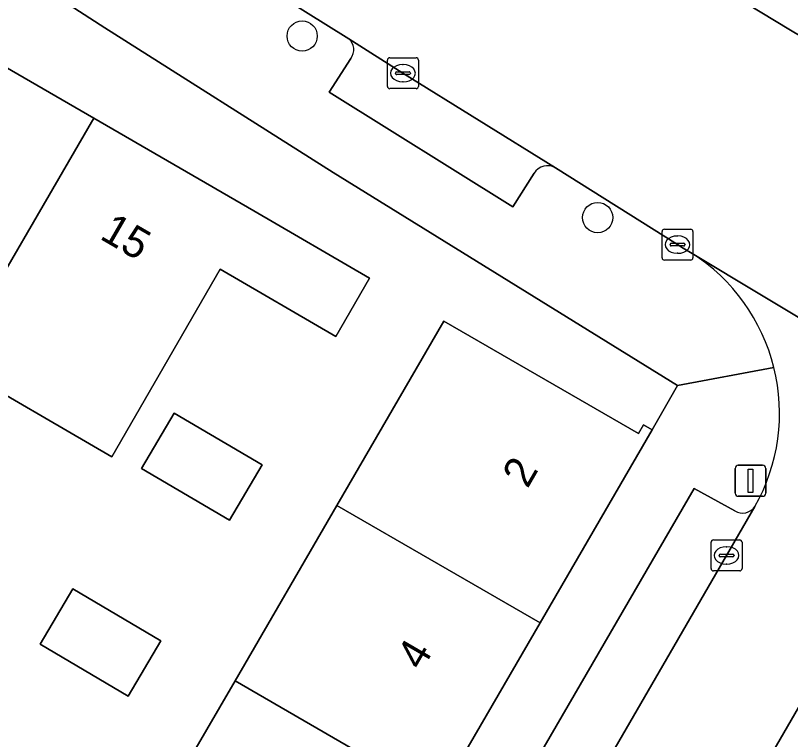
# Model space of a CAD drawing. Extents: x 160023 to 161302, y 384750 to 385707.
# Drawn here: x 160328.19 to 160353.25, y 385096.97 to 385120.37 of the extents above; entities that cross this region are included whole.
import ezdxf

# ---------------------------------------------------------------- set-up
doc = ezdxf.new("R2010")
doc.units = 0
for name, color, linetype in [('IMGEO_Boom', 7, 'Continuous'), ('IMGEO_Erf', 7, 'Continuous'), ('IMGEO_Kolk', 7, 'Continuous'), ('IMGEO_Lichtmast', 7, 'Continuous'), ('IMGEO_Pand', 7, 'Continuous'), ('IMGEO_Pand_nummerreeks', 7, 'Continuous'), ('IMGEO_Parkeervlak_open', 7, 'Continuous'), ('IMGEO_Rijbaan_lokaal_gesloten', 7, 'Continuous'), ('IMGEO_Rijbaan_lokaal_open', 7, 'Continuous'), ('IMGEO_Voetpad_open', 7, 'Continuous')]:
    doc.layers.add(name, color=color, linetype=linetype)

msp = doc.modelspace()

# ---------------------------------------------------------------- linework, layer by layer
at = {"layer": 'IMGEO_Boom'}
for centre in [(160337.46, 385119.709), (160347.014, 385113.841)]:
    msp.add_circle(centre, 0.489, dxfattribs=at)
at = {"layer": 'IMGEO_Erf'}
for points in [[(160324.913, 385073.741), (160330.09, 385070.735), (160334.083, 385077.616), (160332.317, 385078.627), (160331.779, 385077.69), (160328.34, 385079.651), (160329.434, 385081.559), (160332.868, 385079.588), (160335.098, 385083.409), (160328.525, 385087.223), (160331.975, 385093.164), (160335.29, 385098.871), (160338.579, 385104.535), (160342.039, 385110.493), (160348.337, 385106.863), (160348.498, 385107.138), (160348.774, 385106.977), (160349.593, 385108.411), (160338.466, 385115.299), (160331.075, 385119.978), (160323.23, 385125.041)], [(160320.863, 385122.761), (160325.8, 385119.903), (160330.722, 385117.054), (160335.895, 385114.06), (160339.64, 385111.886), (160338.546, 385110.001), (160334.808, 385112.175), (160331.31, 385106.11), (160326.105, 385109.12), (160321.174, 385111.972), (160316.25, 385114.819), (160314.601, 385111.992), (160309.619, 385114.882), (160311.258, 385117.706), (160306.266, 385120.593)]]:
    msp.add_lwpolyline(points, dxfattribs=at)
for points in [[(160332.264, 385105.735), (160333.316, 385107.522), (160336.163, 385105.848), (160335.111, 385104.06)], [(160328.987, 385100.05), (160330.039, 385101.838), (160332.886, 385100.163), (160331.835, 385098.375)]]:
    msp.add_lwpolyline(points, close=True, dxfattribs=at)
at = {"layer": 'IMGEO_Kolk'}
for p, q in [((160340.217, 385118.082), (160340.217, 385118.934)), ((160340.292, 385119.008), (160341.144, 385119.008)), ((160341.218, 385118.934), (160341.218, 385118.082)), ((160340.705, 385118.788), (160340.73, 385118.788)), ((160340.476, 385118.502), (160340.476, 385118.514)), ((160340.914, 385118.465), (160340.516, 385118.465)), ((160340.519, 385118.551), (160340.917, 385118.551)), ((160340.96, 385118.514), (160340.96, 385118.502)), ((160340.728, 385118.228), (160340.703, 385118.228)), ((160341.144, 385118.008), (160340.292, 385118.008)), ((160349.171, 385113.466), (160350.023, 385113.466)), ((160349.096, 385112.54), (160349.096, 385113.392)), ((160349.584, 385113.246), (160349.609, 385113.246)), ((160350.097, 385113.392), (160350.097, 385112.54)), ((160349.355, 385112.96), (160349.355, 385112.972)), ((160349.793, 385112.923), (160349.395, 385112.923)), ((160349.398, 385113.009), (160349.796, 385113.009)), ((160349.839, 385112.972), (160349.839, 385112.96)), ((160349.607, 385112.686), (160349.582, 385112.686)), ((160350.023, 385112.466), (160349.171, 385112.466)), ((160350.756, 385103.421), (160351.608, 385103.421)), ((160350.681, 385102.495), (160350.681, 385103.347)), ((160351.169, 385103.201), (160351.194, 385103.201)), ((160351.682, 385103.347), (160351.682, 385102.495)), ((160350.94, 385102.915), (160350.94, 385102.927)), ((160351.378, 385102.878), (160350.98, 385102.878)), ((160350.983, 385102.964), (160351.381, 385102.964)), ((160351.424, 385102.927), (160351.424, 385102.915)), ((160351.192, 385102.641), (160351.167, 385102.641)), ((160351.608, 385102.421), (160350.756, 385102.421))]:
    msp.add_line(p, q, dxfattribs=at)
for points in [[(160340.217, 385118.082), (160340.217, 385118.934)], [(160340.292, 385119.008), (160341.144, 385119.008)], [(160341.218, 385118.934), (160341.218, 385118.082)], [(160341.144, 385118.008), (160340.292, 385118.008)], [(160349.171, 385113.466), (160350.023, 385113.466)], [(160349.096, 385112.54), (160349.096, 385113.392)], [(160350.097, 385113.392), (160350.097, 385112.54)], [(160350.023, 385112.466), (160349.171, 385112.466)], [(160350.756, 385103.421), (160351.608, 385103.421)], [(160350.681, 385102.495), (160350.681, 385103.347)], [(160351.682, 385103.347), (160351.682, 385102.495)], [(160351.608, 385102.421), (160350.756, 385102.421)]]:
    msp.add_lwpolyline(points, dxfattribs=at)
for centre, radius, start, end in [((160340.294, 385118.932), 0.0765, 91.552, 178.448), ((160340.294, 385118.932), 0.0765, 91.552, 178.448), ((160341.142, 385118.932), 0.0765, 1.552, 88.448), ((160341.142, 385118.932), 0.0765, 1.552, 88.448), ((160340.516, 385118.511), 0.0403, 85.8775, 175.7526), ((160340.513, 385118.501), 0.0366, 178.938, 274.7102), ((160340.917, 385118.508), 0.043, 264.8664, 352.4533), ((160340.921, 385118.513), 0.0386, 1.7309, 96.639), ((160340.294, 385118.084), 0.0765, 181.552, 268.448), ((160340.294, 385118.084), 0.0765, 181.552, 268.448), ((160341.142, 385118.084), 0.0765, 271.552, 358.448), ((160341.142, 385118.084), 0.0765, 271.552, 358.448), ((160349.173, 385113.39), 0.0765, 91.552, 178.448), ((160349.173, 385113.39), 0.0765, 91.552, 178.448), ((160350.021, 385113.39), 0.0765, 1.552, 88.448), ((160350.021, 385113.39), 0.0765, 1.552, 88.448), ((160349.395, 385112.969), 0.0403, 85.8775, 175.7526), ((160349.392, 385112.959), 0.0366, 178.938, 274.7102), ((160349.796, 385112.966), 0.043, 264.8664, 352.4533), ((160349.8, 385112.971), 0.0386, 1.7309, 96.639), ((160349.173, 385112.542), 0.0765, 181.552, 268.448), ((160349.173, 385112.542), 0.0765, 181.552, 268.448), ((160350.021, 385112.542), 0.0765, 271.552, 358.448), ((160350.021, 385112.542), 0.0765, 271.552, 358.448), ((160350.758, 385103.345), 0.0765, 91.552, 178.448), ((160350.758, 385103.345), 0.0765, 91.552, 178.448), ((160351.606, 385103.345), 0.0765, 1.552, 88.448), ((160351.606, 385103.345), 0.0765, 1.552, 88.448), ((160350.98, 385102.924), 0.0403, 85.8775, 175.7526), ((160350.977, 385102.914), 0.0366, 178.938, 274.7102), ((160351.381, 385102.921), 0.043, 264.8664, 352.4533), ((160351.385, 385102.926), 0.0386, 1.7309, 96.639), ((160350.758, 385102.497), 0.0765, 181.552, 268.448), ((160350.758, 385102.497), 0.0765, 181.552, 268.448), ((160351.606, 385102.497), 0.0765, 271.552, 358.448), ((160351.606, 385102.497), 0.0765, 271.552, 358.448)]:
    msp.add_arc(centre, radius, start, end, dxfattribs=at)
for centre, major_axis, ratio, start_param, end_param in [((160340.704, 385118.508), (-0.387, 0.002), 0.722429, 4.712389, 7.853982), ((160340.729, 385118.508), (-0.39, 0.002), 0.717154, 1.570796, 4.712389), ((160349.583, 385112.966), (-0.387, 0.002), 0.722429, 4.712389, 7.853982), ((160349.608, 385112.966), (-0.39, 0.002), 0.717154, 1.570796, 4.712389), ((160351.168, 385102.921), (-0.387, 0.002), 0.722429, 4.712389, 7.853982), ((160351.193, 385102.921), (-0.39, 0.002), 0.717154, 1.570796, 4.712389)]:
    msp.add_ellipse(centre, major_axis=major_axis, ratio=ratio, start_param=start_param, end_param=end_param, dxfattribs=at)
at = {"layer": 'IMGEO_Lichtmast'}
for p, q in [((160351.46, 385104.933), (160351.46, 385105.733)), ((160351.46, 385105.733), (160351.46, 385104.933)), ((160351.56, 385105.833), (160352.35, 385105.833)), ((160352.35, 385105.833), (160351.56, 385105.833)), ((160352.45, 385105.733), (160352.45, 385104.933)), ((160352.45, 385104.933), (160352.45, 385105.733)), ((160352.35, 385104.833), (160351.56, 385104.833)), ((160351.56, 385104.833), (160352.35, 385104.833))]:
    msp.add_line(p, q, dxfattribs=at)
msp.add_lwpolyline([(160351.88, 385105.708), (160352.03, 385105.708), (160352.03, 385104.958), (160351.88, 385104.958), (160351.88, 385105.708)], dxfattribs=at)
for centre, start, end in [((160351.56, 385105.733), 90, 180), ((160351.56, 385105.733), 90, 180), ((160352.35, 385105.733), 0, 90), ((160352.35, 385105.733), 360, 90), ((160351.56, 385104.933), 180, 270), ((160351.56, 385104.933), 180, 270), ((160352.35, 385104.933), 270, 0), ((160352.35, 385104.933), 270, 0)]:
    msp.add_arc(centre, 0.1, start, end, dxfattribs=at)
at = {"layer": 'IMGEO_Pand'}
for points in [[(160330.722, 385117.054), (160325.8, 385119.903), (160321.263, 385112.126), (160321.174, 385111.972), (160326.105, 385109.12)], [(160326.105, 385109.12), (160331.31, 385106.11), (160334.808, 385112.175), (160338.546, 385110.001), (160339.64, 385111.886), (160335.895, 385114.06), (160330.722, 385117.054)], [(160348.774, 385106.977), (160348.498, 385107.138), (160348.337, 385106.863), (160342.039, 385110.493), (160338.579, 385104.535), (160345.154, 385100.738)], [(160332.264, 385105.735), (160335.111, 385104.06), (160336.163, 385105.848), (160333.316, 385107.522)], [(160345.154, 385100.738), (160338.579, 385104.535), (160335.29, 385098.871), (160341.859, 385095.06)], [(160328.987, 385100.05), (160331.835, 385098.375), (160332.886, 385100.163), (160330.039, 385101.838)], [(160341.859, 385095.06), (160335.29, 385098.871), (160331.975, 385093.164), (160338.539, 385089.338)]]:
    msp.add_lwpolyline(points, close=True, dxfattribs=at)
at = {"layer": 'IMGEO_Parkeervlak_open'}
for points in [[(160345.651, 385115.447), (160340.714, 385118.509), (160338.966, 385119.621)], [(160339.031, 385118.986), (160338.336, 385117.891), (160344.268, 385114.185), (160344.958, 385115.276)], [(160351.446, 385104.358), (160350.138, 385105.085), (160344.699, 385095.733), (160345.712, 385095.144)], [(160339.387, 385082.576), (160342.043, 385087.129), (160351.183, 385102.92), (160352.099, 385104.5)], [(160355.976, 385102.245), (160355.29, 385101.073), (160345.014, 385083.339), (160343.285, 385080.295)]]:
    msp.add_lwpolyline(points, dxfattribs=at)
for centre, radius, start, end in [((160338.674, 385119.27), 0.456, 321.4584, 50.2308), ((160345.393, 385115.004), 0.513, 59.7287, 147.9934), ((160351.698, 385104.77), 0.483, 238.5438, 325.993)]:
    msp.add_arc(centre, radius, start, end, dxfattribs=at)
at = {"layer": 'IMGEO_Rijbaan_lokaal_gesloten'}
for points in [[(160373.082, 385108.155), (160362.963, 385114.135), (160353.245, 385119.896), (160345.516, 385124.585)], [(160335.598, 385121.727), (160338.966, 385119.621), (160340.714, 385118.509), (160345.651, 385115.447), (160349.593, 385112.967), (160349.782, 385112.854), (160350.067, 385112.683), (160363.683, 385104.506), (160364.569, 385103.936), (160365.671, 385103.277), (160371.088, 385100.124)]]:
    msp.add_lwpolyline(points, dxfattribs=at)
at = {"layer": 'IMGEO_Rijbaan_lokaal_open'}
for points in [[(160363.683, 385104.506), (160350.067, 385112.683)], [(160352.099, 385104.5), (160351.183, 385102.92), (160342.043, 385087.129), (160339.387, 385082.576), (160338.894, 385081.699), (160336.41, 385077.395), (160333.739, 385072.8), (160315.942, 385042.109), (160311.381, 385034.254), (160308.757, 385029.746), (160308.283, 385028.896), (160306.745, 385026.259), (160297.459, 385010.254), (160295.452, 385006.786), (160294.418, 385005.017)], [(160338.122, 385071.424), (160340.106, 385074.885), (160342.782, 385079.444), (160343.285, 385080.295), (160345.014, 385083.339), (160355.29, 385101.073), (160355.976, 385102.245)]]:
    msp.add_lwpolyline(points, dxfattribs=at)
for centre, radius, start, end in [((160346.768, 385107.519), 6.127, 13.9564, 57.4301), ((160346.772, 385107.52), 6.124, 330.4468, 13.9535)]:
    msp.add_arc(centre, radius, start, end, dxfattribs=at)
at = {"layer": 'IMGEO_Voetpad_open'}
for points in [[(160333.972, 385131.862), (160342.253, 385126.595), (160343.306, 385125.926), (160345.516, 385124.585), (160353.245, 385119.896), (160362.963, 385114.135), (160373.082, 385108.155), (160375.076, 385106.975), (160378.045, 385105.217), (160379.385, 385104.426)], [(160323.23, 385125.041), (160331.075, 385119.978), (160338.466, 385115.299), (160349.593, 385108.411), (160352.715, 385108.997)], [(160338.966, 385119.621), (160335.598, 385121.727)], [(160344.958, 385115.276), (160344.268, 385114.185), (160338.336, 385117.891), (160339.031, 385118.986)], [(160350.067, 385112.683), (160349.782, 385112.854), (160349.593, 385112.967), (160345.651, 385115.447)], [(160352.715, 385108.997), (160349.593, 385108.411), (160348.774, 385106.977), (160345.154, 385100.738), (160341.859, 385095.06), (160338.539, 385089.338), (160335.098, 385083.409), (160332.868, 385079.588), (160332.317, 385078.627), (160334.083, 385077.616), (160330.09, 385070.735), (160326.01, 385063.697), (160326.107, 385063.646)], [(160345.712, 385095.144), (160344.699, 385095.733), (160350.138, 385105.085), (160351.446, 385104.358)]]:
    msp.add_lwpolyline(points, dxfattribs=at)
for centre, radius, start, end in [((160338.674, 385119.27), 0.456, 321.4584, 50.2308), ((160345.393, 385115.004), 0.513, 59.7287, 147.9934), ((160346.768, 385107.519), 6.127, 13.9564, 57.4301), ((160346.772, 385107.52), 6.124, 330.4468, 13.9535), ((160351.698, 385104.77), 0.483, 238.5438, 325.993)]:
    msp.add_arc(centre, radius, start, end, dxfattribs=at)

# ---------------------------------------------------------------- texts
at = {"layer": 'IMGEO_Pand_nummerreeks'}
for s, rotation, p in [('15', 329.9362, (160330.878, 385113.174)), ('2', 59.8743, (160344.746, 385105.057)), ('4', 59.8743, (160341.328, 385099.167))]:
    msp.add_text(s, height=1, rotation=rotation, dxfattribs=at).set_placement(p)

doc.saveas('drawing.dxf')
